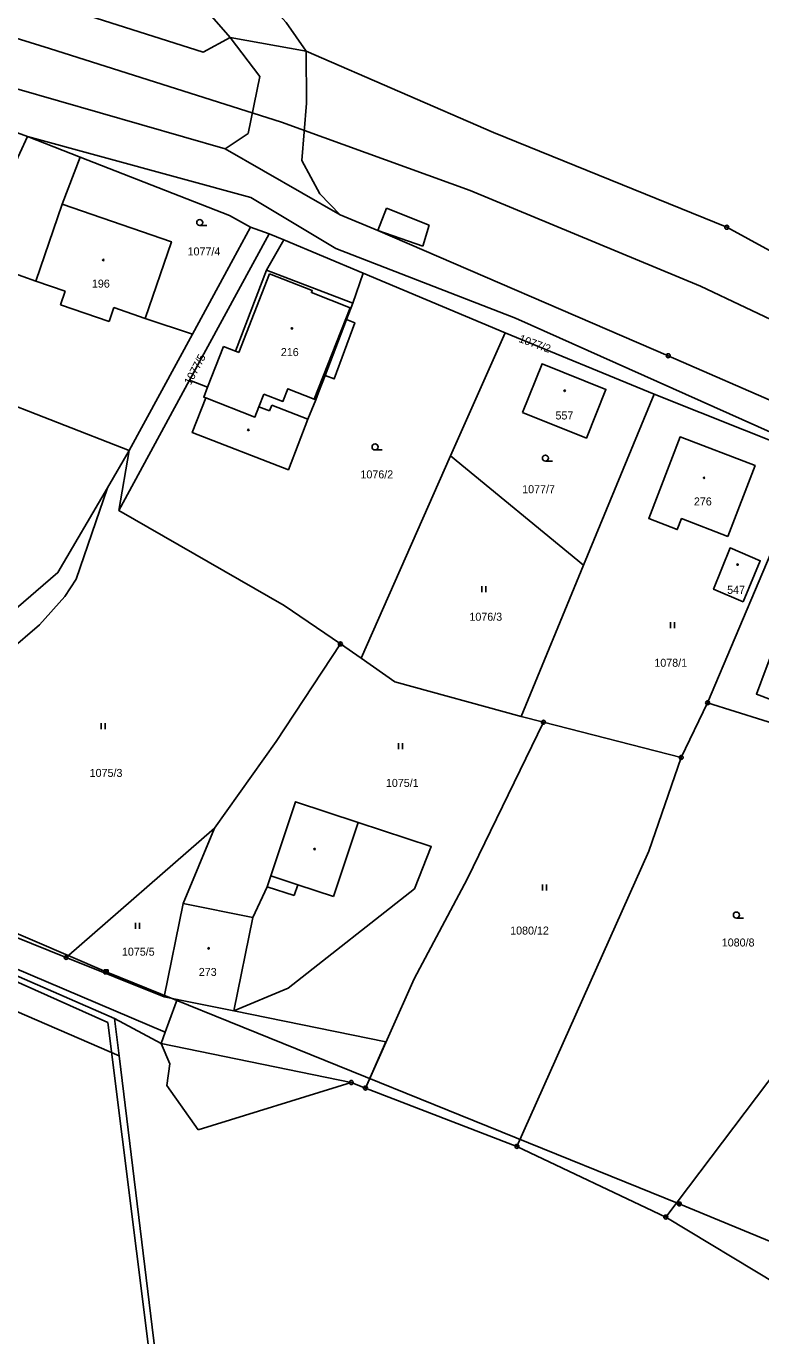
# Model space of a CAD drawing. Extents: x -745926 to -742978, y -968282 to -965689.
# Drawn here: x -744948.1 to -744856.3, y -967249.8 to -967086.2 of the extents above; entities that cross this region are included whole.
import ezdxf

# ---------------------------------------------------------------- set-up
doc = ezdxf.new("R2010")
doc.units = 0
for name, color, linetype in [('Hranice parcel', 7, 'Continuous'), ('Parcelní čísla', 7, 'Continuous'), ('Poz předměty', 7, 'Continuous'), ('Vnitřní kresba', 7, 'Continuous'), ('Věcná břemena k části', 7, 'Continuous'), ('Značky bodu BP', 7, 'Continuous'), ('Značky budov', 7, 'Continuous'), ('Značky kultur', 7, 'Continuous')]:
    doc.layers.add(name, color=color, linetype=linetype)

msp = doc.modelspace()

# ---------------------------------------------------------------- linework, layer by layer
at = {"layer": 'Hranice parcel'}
for p, q in [((-744913.09, -967089.29), (-744922.6, -967087.6)), ((-744947.9, -967099.97), (-744949.62, -967099.33)), ((-744941.32, -967102.54), (-744947.9, -967099.97)), ((-744920.03, -967111.29), (-744917.71, -967112.1)), ((-744915.88, -967112.87), (-744917.71, -967112.1)), ((-744935.18, -967139.19), (-744927.28, -967124.65)), ((-744895.05, -967139.84), (-744888.25, -967124.47)), ((-744888.25, -967124.47), (-744869.64, -967132.13)), ((-744927.66, -967130.38), (-744936.48, -967146.66)), ((-744927.66, -967130.38), (-744925.4, -967131.25)), ((-744878.44, -967153.5), (-744869.64, -967132.13)), ((-744869.64, -967132.13), (-744849.99, -967139.99)), ((-744937.9, -967143.84), (-744935.18, -967139.19)), ((-744935.18, -967139.19), (-744936.48, -967146.66)), ((-744906.23, -967165.11), (-744895.05, -967139.84)), ((-744878.44, -967153.5), (-744895.05, -967139.84)), ((-744862.95, -967170.69), (-744849.99, -967139.99)), ((-744936.48, -967146.66), (-744915.85, -967158.52)), ((-744886.22, -967172.41), (-744878.44, -967153.5)), ((-744915.85, -967158.52), (-744908.82, -967163.34)), ((-744906.23, -967165.11), (-744908.82, -967163.34)), ((-744866.25, -967177.52), (-744862.95, -967170.69)), ((-744828.56, -967181.48), (-744862.95, -967170.69)), ((-744883.45, -967173.12), (-744886.22, -967172.41)), ((-744883.45, -967173.12), (-744866.25, -967177.52)), ((-744943.07, -967202.5), (-744924.53, -967186.35)), ((-744924.53, -967186.35), (-744928.46, -967195.75)), ((-744998.55, -967187.86), (-744936.45, -967214.79)), ((-744868.17, -967234.92), (-744832.63, -967187.9)), ((-744943.07, -967202.5), (-744970.43, -967191.54)), ((-744928.46, -967195.75), (-744930.82, -967207.41)), ((-744930.82, -967207.41), (-744943.07, -967202.5)), ((-744930.82, -967207.41), (-744929.19, -967207.75)), ((-744936.45, -967214.79), (-744937.02, -967210.11)), ((-744937.02, -967210.11), (-744931.21, -967213.26)), ((-744931.21, -967213.26), (-744907.46, -967218.12)), ((-744936.45, -967214.79), (-744926.16, -967299.13)), ((-744907.46, -967218.12), (-744905.68, -967218.81)), ((-744886.77, -967226.1), (-744905.68, -967218.81)), ((-744868.17, -967234.92), (-744886.77, -967226.1)), ((-744854.24, -967243.36), (-744868.17, -967234.92))]:
    msp.add_line(p, q, dxfattribs=at)
for points in [[(-744922.6, -967087.6), (-744928.66, -967080.6), (-744939.99, -967073.81), (-744941.53, -967073.12)], [(-744922.6, -967087.6), (-744925.97, -967089.41), (-744942.85, -967084.03), (-744943.9, -967083.71), (-744945.52, -967083.22)], [(-744913.09, -967089.29), (-744915.6, -967085.72), (-744916.44, -967084.8)], [(-744693.6, -967209.2), (-744707.34, -967200.94), (-744716.41, -967199.92), (-744750.6, -967176.7), (-744790.58, -967150.66), (-744800.6, -967144.47), (-744829.49, -967128.26), (-744860.55, -967111.29), (-744889.69, -967099.44), (-744913.09, -967089.29)], [(-744949.24, -967094.01), (-744923.2, -967101.49), (-744908.83, -967109.73), (-744904.12, -967111.71), (-744867.87, -967127.34), (-744824.27, -967146.35), (-744795.5, -967164.9), (-744758, -967189), (-744715.6, -967218.1), (-744709, -967222.3), (-744714.96, -967227.46), (-744716.65, -967230.33)], [(-744831.9, -967147.24), (-744886.96, -967122.64), (-744909.4, -967113.93), (-744920.02, -967107.58), (-744947.9, -967099.97)], [(-744927.28, -967124.65), (-744933.21, -967122.67), (-744929.91, -967113.11), (-744943.56, -967108.41), (-744941.32, -967102.54)], [(-744941.32, -967102.54), (-744922.66, -967109.81), (-744920.03, -967111.29)], [(-744917.71, -967112.1), (-744925.39, -967126.19), (-744927.66, -967130.38)], [(-744925.64, -967132.6), (-744927.31, -967136.93), (-744915.31, -967141.57), (-744912.86, -967135.26), (-744911.89, -967132.83), (-744911.53, -967131.95), (-744910.72, -967129.81), (-744909.61, -967130.24), (-744907.03, -967123.21), (-744908.05, -967122.82), (-744907.27, -967120.77), (-744918.05, -967116.66), (-744915.88, -967112.87)], [(-744927.28, -967124.65), (-744922.2, -967115.29), (-744920.03, -967111.29)], [(-744888.25, -967124.47), (-744905.99, -967117.02), (-744915.88, -967112.87)], [(-744962.66, -967128.49), (-744961.06, -967129.11), (-744957.1, -967130.65), (-744953.15, -967132.19), (-744935.18, -967139.19)], [(-744886.08, -967134.42), (-744883.63, -967128.34), (-744875.65, -967131.54), (-744878.09, -967137.63), (-744886.08, -967134.42)], [(-744925.4, -967131.25), (-744925.89, -967132.51), (-744925.64, -967132.6)], [(-744860.41, -967149.91), (-744857.01, -967141.07), (-744866.39, -967137.47), (-744870.31, -967147.67), (-744866.74, -967149.05), (-744866.21, -967147.68), (-744860.41, -967149.91)], [(-744978.14, -967183.77), (-744944.1, -967154.43), (-744937.9, -967143.84)], [(-744937.9, -967143.84), (-744941.83, -967155.25), (-744943.23, -967157.4), (-744946.4, -967160.94), (-744950.26, -967164.28), (-744963.14, -967174.51), (-744965.88, -967176.74), (-744970.19, -967179.31), (-744972.6, -967179.84), (-744977.02, -967184.7), (-744978.14, -967183.77)], [(-744831.9, -967147.24), (-744839.39, -967150.22), (-744841.94, -967156.05), (-744846.44, -967154.36), (-744846.63, -967154.88), (-744851.14, -967153.19), (-744852.85, -967157.72), (-744852.43, -967157.87), (-744855.62, -967166.35), (-744856.85, -967169.61), (-744848.47, -967172.76), (-744836.16, -967169.58), (-744838.29, -967158.3), (-744835.56, -967152.95), (-744830.59, -967150.33), (-744826.99, -967148.18)], [(-744858.51, -967158.06), (-744862.2, -967156.51), (-744860.15, -967151.35), (-744856.37, -967152.95), (-744858.51, -967158.06)], [(-744908.82, -967163.34), (-744916.82, -967175.52), (-744924.53, -967186.35)], [(-744886.22, -967172.41), (-744902, -967168.08), (-744906.23, -967165.11)], [(-744905.68, -967218.81), (-744899.62, -967205.17), (-744892.99, -967192.74), (-744883.45, -967173.12)], [(-744866.25, -967177.52), (-744870.28, -967189.22), (-744886.77, -967226.1)], [(-744929.19, -967207.75), (-744922.11, -967209.18), (-744915.34, -967206.34), (-744899.56, -967193.92), (-744897.46, -967188.65), (-744906.6, -967185.64), (-744914.43, -967183.05), (-744917.49, -967192.29), (-744917.94, -967193.66), (-744919.74, -967197.52), (-744928.46, -967195.75)], [(-744995.87, -967184.09), (-744962.89, -967198.83), (-744937.02, -967210.11)], [(-744931.21, -967213.26), (-744930.68, -967211.82), (-744930.23, -967210.59), (-744929.19, -967207.75)]]:
    msp.add_lwpolyline(points, dxfattribs=at)
at = {"layer": 'Poz předměty'}
for p, q in [((-744965.76, -967082.64), (-744945.15, -967088.95)), ((-744945.15, -967088.95), (-744916.15, -967098.16)), ((-744916.15, -967098.16), (-744892.59, -967106.71)), ((-744892.59, -967106.71), (-744863.84, -967118.64)), ((-744863.84, -967118.64), (-744832.7, -967133.45)), ((-745004.33, -967175.76), (-744938.08, -967204.29)), ((-744938.33, -967204.04), (-744937.83, -967204.04)), ((-744938.33, -967204.54), (-744938.33, -967204.04)), ((-744938.33, -967204.14), (-744937.83, -967204.14)), ((-744938.33, -967204.24), (-744937.83, -967204.24)), ((-744938.33, -967204.34), (-744937.83, -967204.34)), ((-744938.33, -967204.44), (-744937.83, -967204.44)), ((-744938.23, -967204.54), (-744938.23, -967204.04)), ((-744938.13, -967204.54), (-744938.13, -967204.04)), ((-744938.08, -967204.29), (-744866.49, -967233.28)), ((-744938.03, -967204.54), (-744938.03, -967204.04)), ((-744937.93, -967204.54), (-744937.93, -967204.04)), ((-744937.83, -967204.54), (-744937.83, -967204.04)), ((-744938.33, -967204.54), (-744937.83, -967204.54)), ((-744866.49, -967233.28), (-744813.86, -967255.12))]:
    msp.add_line(p, q, dxfattribs=at)
for radius in [0.25, 0.2, 0.15, 0.1, 0.05]:
    msp.add_circle((-744866.49, -967233.28), radius, dxfattribs=at)
at = {"layer": 'Vnitřní kresba'}
for p, q in [((-744918.86, -967092.47), (-744922.6, -967087.6)), ((-744913.09, -967089.29), (-744913.03, -967095.77)), ((-744920.32, -967099.58), (-744918.86, -967092.47)), ((-744913.03, -967095.77), (-744913.61, -967102.96)), ((-744923.2, -967101.49), (-744920.32, -967099.58)), ((-744947.9, -967099.97), (-744954.9, -967115.13)), ((-744913.61, -967102.96), (-744911.38, -967107.13)), ((-744911.38, -967107.13), (-744908.83, -967109.73)), ((-744946.86, -967118.02), (-744943.56, -967108.41)), ((-744904.12, -967111.71), (-744903.07, -967108.91)), ((-744903.07, -967108.91), (-744897.72, -967111.01)), ((-744897.72, -967111.01), (-744898.53, -967113.65)), ((-744898.53, -967113.65), (-744904.12, -967111.71)), ((-744954.9, -967115.13), (-744946.86, -967118.02)), ((-744918.05, -967116.66), (-744921.9, -967126.76)), ((-744917.65, -967117.09), (-744921.5, -967126.92)), ((-744907.27, -967120.77), (-744905.99, -967117.02)), ((-744943.2, -967119.28), (-744946.86, -967118.02)), ((-744943.78, -967120.97), (-744943.2, -967119.28)), ((-744937.71, -967123.06), (-744943.78, -967120.97)), ((-744937.11, -967121.33), (-744937.71, -967123.06)), ((-744933.21, -967122.67), (-744937.11, -967121.33)), ((-744907.6, -967121.35), (-744912.07, -967132.76)), ((-744908.05, -967122.82), (-744910.72, -967129.81)), ((-744923.41, -967126.17), (-744925.4, -967131.25)), ((-744921.9, -967126.76), (-744923.41, -967126.17)), ((-744921.5, -967126.92), (-744921.9, -967126.76)), ((-744919, -967133.72), (-744918.37, -967132.12)), ((-744917.66, -967134.24), (-744919, -967133.72)), ((-744917.66, -967134.24), (-744917.38, -967133.51)), ((-744917.38, -967133.51), (-744912.86, -967135.26)), ((-744912.07, -967132.76), (-744911.89, -967132.83)), ((-744937.88, -967210.62), (-744996.72, -967184.38)), ((-744930.68, -967211.82), (-744995.87, -967184.09)), ((-744906.6, -967185.64), (-744909.66, -967194.89)), ((-744914.12, -967193.41), (-744917.49, -967192.29)), ((-744914.57, -967194.78), (-744917.94, -967193.66)), ((-744914.12, -967193.41), (-744914.57, -967194.78)), ((-744909.66, -967194.89), (-744914.12, -967193.41)), ((-744919.74, -967197.52), (-744922.11, -967209.18)), ((-744926.75, -967299.21), (-744937.88, -967210.62)), ((-744930.12, -967215.8), (-744931.21, -967213.26)), ((-744930.5, -967218.51), (-744930.12, -967215.8)), ((-744926.59, -967224.05), (-744930.5, -967218.51)), ((-744907.46, -967218.12), (-744926.59, -967224.05))]:
    msp.add_line(p, q, dxfattribs=at)
for points in [[(-744917.65, -967117.09), (-744912.33, -967119.17), (-744912.44, -967119.45), (-744907.6, -967121.35)], [(-744918.37, -967132.12), (-744915.99, -967133.05), (-744915.37, -967131.47), (-744912.07, -967132.76)], [(-744925.64, -967132.6), (-744919.5, -967135.01), (-744919, -967133.72)]]:
    msp.add_lwpolyline(points, dxfattribs=at)
at = {"layer": 'Věcná břemena k části'}
msp.add_lwpolyline([(-744922.11, -967209.18), (-744929.19, -967207.75), (-744930.23, -967210.59), (-744930.68, -967211.82), (-744931.21, -967213.26), (-744907.46, -967218.12), (-744905.68, -967218.81), (-744903.13, -967213.06)], close=True, dxfattribs=at)
at = {"layer": 'Značky bodu BP'}
for centre, radius in [((-744860.55, -967111.29), 0.25), ((-744860.55, -967111.29), 0.0152), ((-744867.87, -967127.34), 0.25), ((-744867.87, -967127.34), 0.0152), ((-744908.82, -967163.34), 0.25), ((-744908.82, -967163.34), 0.0152), ((-744862.95, -967170.69), 0.25), ((-744862.95, -967170.69), 0.0152), ((-744883.45, -967173.12), 0.25), ((-744883.45, -967173.12), 0.0152), ((-744866.25, -967177.52), 0.25), ((-744866.25, -967177.52), 0.0152), ((-744943.07, -967202.5), 0.25), ((-744943.07, -967202.5), 0.0152), ((-744907.46, -967218.12), 0.25), ((-744907.46, -967218.12), 0.0152), ((-744905.68, -967218.81), 0.25), ((-744905.68, -967218.81), 0.0152), ((-744886.77, -967226.1), 0.25), ((-744886.77, -967226.1), 0.0152), ((-744868.17, -967234.92), 0.25), ((-744868.17, -967234.92), 0.0152)]:
    msp.add_circle(centre, radius, dxfattribs=at)
at = {"layer": 'Značky budov'}
for centre in [(-744938.44, -967115.38), (-744914.87, -967123.93), (-744880.8, -967131.72), (-744920.31, -967136.6), (-744863.4, -967142.59), (-744859.21, -967153.42), (-744912.04, -967188.96), (-744925.28, -967201.36)]:
    msp.add_circle(centre, 0.0875, dxfattribs=at)
at = {"layer": 'Značky kultur'}
for p, q in [((-744926.39, -967111.08), (-744925.51, -967111.08)), ((-744904.48, -967139.11), (-744903.6, -967139.11)), ((-744883.21, -967140.51), (-744882.33, -967140.51)), ((-744891.14, -967156.89), (-744891.14, -967156.14)), ((-744890.64, -967156.89), (-744890.64, -967156.14)), ((-744867.57, -967161.37), (-744867.57, -967160.62)), ((-744867.07, -967161.37), (-744867.07, -967160.62)), ((-744938.68, -967173.97), (-744938.68, -967173.22)), ((-744938.18, -967173.97), (-744938.18, -967173.22)), ((-744901.55, -967176.47), (-744901.55, -967175.72)), ((-744901.05, -967176.47), (-744901.05, -967175.72)), ((-744883.59, -967194.12), (-744883.59, -967193.37)), ((-744883.08, -967194.12), (-744883.08, -967193.37)), ((-744859.36, -967197.58), (-744858.48, -967197.58)), ((-744934.41, -967198.92), (-744934.41, -967198.17)), ((-744933.91, -967198.92), (-744933.91, -967198.17))]:
    msp.add_line(p, q, dxfattribs=at)
for centre in [(-744926.39, -967110.7), (-744904.48, -967138.73), (-744883.21, -967140.13), (-744859.36, -967197.2)]:
    msp.add_circle(centre, 0.375, dxfattribs=at)

# ---------------------------------------------------------------- texts
at = {"layer": 'Parcelní čísla'}
for s, p in [('1077/4', (-744927.9, -967114.81)), ('196', (-744939.85, -967118.83)), ('216', (-744916.25, -967127.38)), ('557', (-744881.95, -967135.3)), ('1076/2', (-744906.31, -967142.66)), ('1077/7', (-744886.11, -967144.51)), ('276', (-744864.66, -967146.04)), ('547', (-744860.51, -967157.08)), ('1076/3', (-744892.7, -967160.44)), ('1078/1', (-744869.6, -967166.19)), ('1075/3', (-744940.13, -967179.95)), ('1075/1', (-744903.13, -967181.2)), ('1080/12', (-744887.61, -967199.64)), ('1080/8', (-744861.18, -967201.13)), ('1075/5', (-744936.1, -967202.28)), ('273', (-744926.5, -967204.81))]:
    msp.add_text(s, height=1, dxfattribs=at).set_placement(p)
for s, rotation, p in [('1077/2', 340, (-744886.61, -967125.6)), ('1077/5', 62, (-744927.51, -967131.07))]:
    msp.add_text(s, height=1, rotation=rotation, dxfattribs=at).set_placement(p)

doc.saveas('drawing.dxf')
